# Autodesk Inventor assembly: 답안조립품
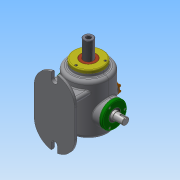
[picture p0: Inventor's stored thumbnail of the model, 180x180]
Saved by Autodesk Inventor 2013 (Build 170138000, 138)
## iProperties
Created: 2018-02
Part Number: 답안조립품
Document SubType Name: Assembly
Designer: Administrator
Author: Administrator
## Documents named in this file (16)
- C:\Users\Administrator\Desktop\380208V1006\답안조립품.iam
- C:\Users\Administrator\Desktop\380208V1006\본체.ipt
- C:\Users\Administrator\Desktop\380208V1006\베어링 6205.ipt
- 베어링 6205.ipt
- C:\Users\Administrator\Desktop\380208V1006\본체커버.ipt
- C:\Users\Administrator\Desktop\380208V1006\볼트 M4.ipt
- C:\Users\Administrator\Desktop\380208V1006\부시.ipt
- C:\Users\Administrator\Desktop\380208V1006\상부 캡.ipt
- C:\Users\Administrator\Desktop\380208V1006\슬라이드 커버.ipt
- C:\Users\Administrator\Desktop\380208V1006\슬라이드.ipt
- C:\Users\Administrator\Desktop\380208V1006\오일실.ipt
- 오일실.ipt
- C:\Users\Administrator\Desktop\380208V1006\축 커버-1.ipt
- C:\Users\Administrator\Desktop\380208V1006\축 커버-2.ipt
- C:\Users\Administrator\Desktop\380208V1006\편심축.ipt
- C:\Users\Administrator\Desktop\380208V1006\가변스프링.ipt
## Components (1 placed, 1 different names)
1. 가변스프링:1
